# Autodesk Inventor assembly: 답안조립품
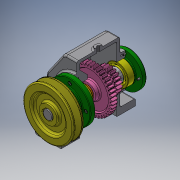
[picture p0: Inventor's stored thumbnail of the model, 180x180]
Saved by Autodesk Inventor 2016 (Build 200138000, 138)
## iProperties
Created: 2022-12
Part Number: 답안조립품
Material: 일반
Document SubType Name: Assembly
Designer: Windows7
Author: Windows7
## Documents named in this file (14)
- C:\Users\Windows7\Desktop\721206V1010\답안조립품.iam
- C:\Users\Windows7\Desktop\721206V1010\본체.ipt
- C:\Users\Windows7\Desktop\721206V1010\앞커버.ipt
- C:\Users\Windows7\Desktop\721206V1010\뒤커버.ipt
- C:\Users\Windows7\Desktop\721206V1010\오일 실 17 x 32 x 8.ipt
- C:\Users\Windows7\Desktop\721206V1010\볼트 M3 x 8.ipt
- C:\Users\Windows7\Desktop\721206V1010\축.ipt
- C:\Users\Windows7\Desktop\721206V1010\키 - 5 x 5 x 18.ipt
- C:\Users\Windows7\Desktop\721206V1010\키 - 6 x 6 x 22.ipt
- C:\Users\Windows7\Desktop\721206V1010\V-벨트풀리.ipt
- C:\Users\Windows7\Desktop\721206V1010\멈춤나사 - M4x10.ipt
- C:\Users\Windows7\Desktop\721206V1010\칼라.ipt
- C:\Users\Windows7\Desktop\721206V1010\베어링 6203.ipt
- C:\Users\Windows7\Desktop\721206V1010\스퍼기어.ipt
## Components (9 placed, 2 different names)
1. V-벨트풀리:2
2. ISO 4762 M3 x 8:1
3. ISO 4762 M3 x 8:3
4. ISO 4762 M3 x 8:4
5. ISO 4762 M3 x 8:5
6. ISO 4762 M3 x 8:2
7. ISO 4762 M3 x 8:6
8. ISO 4762 M3 x 8:7
9. ISO 4762 M3 x 8:8
